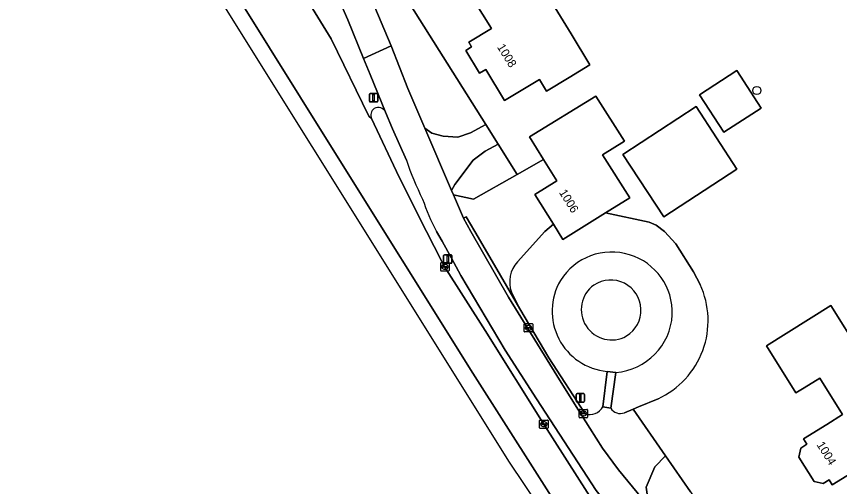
# Model space of a CAD drawing. Extents: x 157767 to 159172, y 387839 to 389425.
# Drawn here: x 158307.1 to 158404.2, y 387969.9 to 388025.4 of the extents above; entities that cross this region are included whole.
import ezdxf

# ---------------------------------------------------------------- set-up
doc = ezdxf.new("R2010")
doc.units = 0
for name, color, linetype in [('IMGEO_Berm_groen', 7, 'Continuous'), ('IMGEO_Berm_open', 7, 'Continuous'), ('IMGEO_Boom', 7, 'Continuous'), ('IMGEO_Erf', 7, 'Continuous'), ('IMGEO_Fietspad_gesloten', 7, 'Continuous'), ('IMGEO_Fietspad_open', 7, 'Continuous'), ('IMGEO_Groenvoorziening', 7, 'Continuous'), ('IMGEO_Hek', 7, 'Continuous'), ('IMGEO_Kolk', 7, 'Continuous'), ('IMGEO_Lichtmast', 7, 'Continuous'), ('IMGEO_Pand', 7, 'Continuous'), ('IMGEO_Pand_nummerreeks', 7, 'Continuous'), ('IMGEO_Rijbaan_lokaal_open', 7, 'Continuous'), ('IMGEO_Rijbaan_regionaal_gesloten', 7, 'Continuous'), ('IMGEO_Verkeersbordpaal', 7, 'Continuous'), ('IMGEO_Voetpad_halfverhard', 7, 'Continuous'), ('IMGEO_Voetpad_op_trap', 7, 'Continuous'), ('IMGEO_Voetpad_open', 7, 'Continuous')]:
    doc.layers.add(name, color=color, linetype=linetype)

msp = doc.modelspace()

# ---------------------------------------------------------------- linework, layer by layer
at = {"layer": 'IMGEO_Berm_groen'}
for points in [[(158346.988, 388032.11), (158351.304, 388021.92), (158353.257, 388016.869), (158355.265, 388012.187), (158356.096, 388011.587), (158357.419, 388011.256), (158359.167, 388011.114), (158360.678, 388011.634), (158362.458, 388012.624), (158347.36, 388036.66)], [(158346.166, 388024.99), (158343.238, 388031.743), (158341.771, 388034.966), (158338.107, 388032.717), (158344.205, 388022.734), (158348.667, 388013.632), (158348.975, 388013.341)], [(158350.634, 388014.091), (158348.806, 388018.518), (158348.022, 388020.44), (158346.166, 388024.99)]]:
    msp.add_lwpolyline(points, dxfattribs=at)
for centre, radius, start, end in [((158349.939, 388013.717), 1.034, 128.90367, 201.31806), ((158349.767, 388013.698), 0.952, 24.36885, 120.09544)]:
    msp.add_arc(centre, radius, start, end, dxfattribs=at)
at = {"layer": 'IMGEO_Berm_open'}
for points in [[(158353.103, 388008.418), (158351.446, 388012.126), (158350.634, 388014.091)], [(158348.975, 388013.341), (158352.222, 388006.425), (158355.483, 388000), (158357.278, 387996.464), (158357.565, 387995.899), (158362.406, 387988.305), (158369.454, 387977.028), (158374.434, 387969.222), (158376.58, 387965.96)], [(158368.454, 387980.231), (158364.771, 387985.981), (158359.525, 387994.789), (158358.421, 387996.854), (158357.304, 387998.859), (158356.652, 388000)], [(158377.656, 387966.667), (158375.484, 387969.385), (158368.454, 387980.231)]]:
    msp.add_lwpolyline(points, dxfattribs=at)
for centre, radius, start, end in [((158349.939, 388013.717), 1.034, 128.90367, 201.31806), ((158349.767, 388013.698), 0.952, 24.36885, 120.09544), ((158386.09, 388019.432), 34.777, 198.46324, 206.67381), ((158377.508, 388011.204), 23.675, 198.17348, 208.24543)]:
    msp.add_arc(centre, radius, start, end, dxfattribs=at)
at = {"layer": 'IMGEO_Boom'}
msp.add_circle((158394.47, 388016.645), 0.489, dxfattribs=at)
at = {"layer": 'IMGEO_Erf'}
for points in [[(158391.002, 388072.621), (158386.634, 388069.473), (158380.196, 388064.831), (158347.36, 388036.66), (158362.458, 388012.624), (158363.916, 388010.303), (158366.166, 388006.72), (158369.284, 388008.484), (158367.637, 388011.156), (158375.48, 388015.988), (158378.849, 388010.676), (158376.257, 388009.033), (158379.47, 388003.965), (158376.609, 388002.185), (158381.757, 388001.103), (158382.595, 388000.747), (158383.581, 388000), (158384.921, 387998.535), (158386.981, 387995.22), (158387.776, 387993.732)], [(158382.802, 387980.241), (158380.487, 387979.276), (158379.876, 387979.021), (158383.679, 387973.511), (158386.626, 387969.24), (158394.403, 387957.97), (158412.383, 387968.073), (158417.684, 387971.05), (158428.795, 387977.293), (158429.92, 387977.925), (158434.455, 387980.473), (158440.859, 387984.071), (158441.223, 387984.276), (158446.112, 387987.022), (158456.939, 387993.105), (158451.954, 388000), (158401.091, 388069.402)]]:
    msp.add_lwpolyline(points, dxfattribs=at)
for points in [[(158374.757, 388019.68), (158372.308, 388018.195), (158369.622, 388016.566), (158368.792, 388017.933), (158364.696, 388015.448), (158362.455, 388019.143), (158361.741, 388018.71), (158360.122, 388021.379), (158360.797, 388021.788), (158360.454, 388022.354), (158363.126, 388023.975), (158359.773, 388029.4), (158364.63, 388032.402), (158365.156, 388031.552), (158367.924, 388033.265), (158370.993, 388028.308), (158369.924, 388027.647), (158370.67, 388026.418), (158372.54, 388023.336)], [(158394.973, 388014.577), (158390.582, 388011.721), (158387.711, 388016.135), (158392.102, 388018.991)], [(158392.124, 388007.366), (158383.483, 388001.712), (158378.63, 388009.099), (158387.322, 388014.753)], [(158406.706, 387985.675), (158405.452, 387984.89), (158408.144, 387980.587), (158411.548, 387975.185), (158407.607, 387972.719), (158406.42, 387971.976), (158404.063, 387970.502), (158403.368, 387970.067), (158403.001, 387970.655), (158402.289, 387970.21), (158401.232, 387970.468), (158399.428, 387973.35), (158399.667, 387974.419), (158400.37, 387974.859), (158399.977, 387975.486), (158402.732, 387977.21), (158404.58, 387978.366), (158401.888, 387982.667), (158400.04, 387981.511), (158399.091, 387980.917), (158395.593, 387986.507), (158403.206, 387991.27)]]:
    msp.add_lwpolyline(points, close=True, dxfattribs=at)
msp.add_arc((158378.575, 387989.462), 10.144, 294.62846, 24.89466, dxfattribs=at)
at = {"layer": 'IMGEO_Fietspad_gesloten'}
msp.add_lwpolyline([(158340.514, 388037.486), (158341.063, 388036.409), (158341.771, 388034.966), (158343.238, 388031.743), (158346.166, 388024.99), (158348.022, 388020.44), (158351.304, 388021.92), (158346.988, 388032.11)], dxfattribs=at)
at = {"layer": 'IMGEO_Fietspad_open'}
for points in [[(158365.138, 387992.225), (158360.688, 387999.997), (158359.827, 388001.551), (158358.642, 388004.313), (158358.423, 388004.824), (158355.265, 388012.187), (158353.257, 388016.869), (158351.304, 388021.92), (158348.022, 388020.44), (158348.806, 388018.518), (158350.634, 388014.091), (158351.446, 388012.126), (158353.103, 388008.418)], [(158356.652, 388000), (158357.304, 387998.859), (158358.421, 387996.854), (158359.525, 387994.789), (158364.771, 387985.981), (158368.454, 387980.231), (158375.484, 387969.385), (158377.656, 387966.667), (158381.586, 387962.012), (158385.061, 387958.273), (158386.178, 387956.878), (158389.083, 387958.681), (158382.54, 387966.471), (158378.147, 387971.847), (158376.253, 387974.417), (158374.768, 387976.744), (158373.35, 387979.008), (158370.858, 387982.984), (158365.138, 387992.225)]]:
    msp.add_lwpolyline(points, dxfattribs=at)
for centre, radius, start, end in [((158386.09, 388019.432), 34.777, 198.46324, 206.67381), ((158377.508, 388011.204), 23.675, 198.17348, 208.24543)]:
    msp.add_arc(centre, radius, start, end, dxfattribs=at)
at = {"layer": 'IMGEO_Groenvoorziening'}
msp.add_lwpolyline([(158358.642, 388004.313), (158361.035, 388003.817), (158366.166, 388006.72), (158363.916, 388010.303), (158362.379, 388009.46), (158360.962, 388008.42), (158358.815, 388005.531), (158358.423, 388004.824)], close=True, dxfattribs=at)
for points in [[(158383.581, 388000), (158382.595, 388000.747), (158381.757, 388001.103), (158376.609, 388002.185), (158371.564, 387999.047), (158370.45, 388000.838), (158369.425, 388000), (158366.221, 387996.405)], [(158387.776, 387993.732), (158386.981, 387995.22), (158384.921, 387998.535), (158383.581, 388000)], [(158365.501, 387992.822), (158366.481, 387990.875), (158369.912, 387985.089), (158374.192, 387978.444)], [(158376.292, 387979.293), (158376.782, 387983.471)], [(158377.816, 387983.342), (158377.221, 387979.137)], [(158378.836, 387978.588), (158379.876, 387979.021), (158380.487, 387979.276), (158382.802, 387980.241)], [(158386.626, 387969.24), (158383.679, 387973.511), (158382.408, 387972.2), (158381.416, 387969.789), (158381.605, 387968.419), (158381.816, 387967.785), (158382.54, 387966.471), (158389.083, 387958.681), (158390.866, 387956.568), (158394.093, 387952.069), (158438.678, 387886.742), (158446.315, 387875.553), (158447.84, 387876.589), (158451.143, 387878.831), (158405.61, 387947.322)]]:
    msp.add_lwpolyline(points, dxfattribs=at)
for centre, radius, start, end in [((158377.347, 387990.422), 7.145, 357.84095, 148.02132), ((158368.759, 387994.031), 3.475, 136.91356, 200.36204), ((158377.438, 387990.581), 7.14, 149.48772, 264.72601), ((158378.575, 387989.462), 10.144, 294.62846, 24.89466), ((158377.254, 387990.564), 7.244, 274.44555, 356.74435), ((158374.723, 387980.153), 1.79, 252.75877, 331.26679), ((158378.356, 387979.827), 1.329, 211.28641, 291.16389)]:
    msp.add_arc(centre, radius, start, end, dxfattribs=at)
at = {"layer": 'IMGEO_Hek'}
for points in [[(158383.679, 387973.511), (158379.876, 387979.021)], [(158386.626, 387969.24), (158383.679, 387973.511)]]:
    msp.add_lwpolyline(points, dxfattribs=at)
at = {"layer": 'IMGEO_Kolk'}
for p, q in [((158357.143, 387995.396), (158357.143, 387996.248)), ((158357.218, 387996.322), (158358.07, 387996.322)), ((158357.402, 387995.816), (158357.402, 387995.828)), ((158357.84, 387995.779), (158357.442, 387995.779)), ((158357.445, 387995.865), (158357.843, 387995.865)), ((158357.631, 387996.102), (158357.656, 387996.102)), ((158357.886, 387995.828), (158357.886, 387995.816)), ((158358.144, 387996.248), (158358.144, 387995.396)), ((158358.07, 387995.322), (158357.218, 387995.322)), ((158357.654, 387995.542), (158357.629, 387995.542)), ((158367.009, 387988.198), (158367.009, 387989.05)), ((158367.084, 387989.124), (158367.936, 387989.124)), ((158367.497, 387988.904), (158367.522, 387988.904)), ((158368.01, 387989.05), (158368.01, 387988.198)), ((158367.936, 387988.124), (158367.084, 387988.124)), ((158367.268, 387988.618), (158367.268, 387988.63)), ((158367.706, 387988.581), (158367.308, 387988.581)), ((158367.311, 387988.667), (158367.709, 387988.667)), ((158367.52, 387988.344), (158367.495, 387988.344)), ((158367.752, 387988.63), (158367.752, 387988.618)), ((158373.481, 387978.058), (158373.481, 387978.91)), ((158373.556, 387978.984), (158374.408, 387978.984)), ((158373.74, 387978.478), (158373.74, 387978.49)), ((158374.178, 387978.441), (158373.78, 387978.441)), ((158373.783, 387978.527), (158374.181, 387978.527)), ((158373.992, 387978.204), (158373.967, 387978.204)), ((158373.969, 387978.764), (158373.994, 387978.764)), ((158374.224, 387978.49), (158374.224, 387978.478)), ((158374.482, 387978.91), (158374.482, 387978.058)), ((158368.824, 387976.801), (158368.824, 387977.653)), ((158368.899, 387977.727), (158369.751, 387977.727)), ((158369.083, 387977.221), (158369.083, 387977.233)), ((158369.521, 387977.184), (158369.123, 387977.184)), ((158369.126, 387977.27), (158369.524, 387977.27)), ((158369.312, 387977.507), (158369.337, 387977.507)), ((158369.567, 387977.233), (158369.567, 387977.221)), ((158369.825, 387977.653), (158369.825, 387976.801)), ((158374.408, 387977.984), (158373.556, 387977.984)), ((158369.751, 387976.727), (158368.899, 387976.727)), ((158369.335, 387976.947), (158369.31, 387976.947))]:
    msp.add_line(p, q, dxfattribs=at)
for points in [[(158357.143, 387995.396), (158357.143, 387996.248)], [(158357.218, 387996.322), (158358.07, 387996.322)], [(158358.144, 387996.248), (158358.144, 387995.396)], [(158358.07, 387995.322), (158357.218, 387995.322)], [(158367.009, 387988.198), (158367.009, 387989.05)], [(158367.084, 387989.124), (158367.936, 387989.124)], [(158368.01, 387989.05), (158368.01, 387988.198)], [(158367.936, 387988.124), (158367.084, 387988.124)], [(158373.481, 387978.058), (158373.481, 387978.91)], [(158373.556, 387978.984), (158374.408, 387978.984)], [(158374.482, 387978.91), (158374.482, 387978.058)], [(158368.824, 387976.801), (158368.824, 387977.653)], [(158368.899, 387977.727), (158369.751, 387977.727)], [(158369.825, 387977.653), (158369.825, 387976.801)], [(158374.408, 387977.984), (158373.556, 387977.984)], [(158369.751, 387976.727), (158368.899, 387976.727)]]:
    msp.add_lwpolyline(points, dxfattribs=at)
for centre, radius, start, end in [((158357.22, 387996.246), 0.0765, 91.55205, 178.44795), ((158357.22, 387996.246), 0.0765, 91.55205, 178.44795), ((158357.442, 387995.825), 0.0403, 85.87752, 175.75265), ((158357.439, 387995.815), 0.0366, 178.93798, 274.71019), ((158357.843, 387995.822), 0.043, 264.86636, 352.45326), ((158357.847, 387995.827), 0.0386, 1.73085, 96.63898), ((158358.068, 387996.246), 0.0765, 1.55205, 88.44795), ((158358.068, 387996.246), 0.0765, 1.55205, 88.44795), ((158357.22, 387995.398), 0.0765, 181.55205, 268.44795), ((158357.22, 387995.398), 0.0765, 181.55205, 268.44795), ((158358.068, 387995.398), 0.0765, 271.55205, 358.44795), ((158358.068, 387995.398), 0.0765, 271.55205, 358.44795), ((158367.086, 387989.048), 0.0765, 91.55205, 178.44795), ((158367.086, 387989.048), 0.0765, 91.55205, 178.44795), ((158367.934, 387989.048), 0.0765, 1.55205, 88.44795), ((158367.934, 387989.048), 0.0765, 1.55205, 88.44795), ((158367.086, 387988.2), 0.0765, 181.55205, 268.44795), ((158367.086, 387988.2), 0.0765, 181.55205, 268.44795), ((158367.308, 387988.627), 0.0403, 85.87752, 175.75265), ((158367.305, 387988.617), 0.0366, 178.93798, 274.71019), ((158367.709, 387988.624), 0.043, 264.86636, 352.45326), ((158367.713, 387988.629), 0.0386, 1.73085, 96.63898), ((158367.934, 387988.2), 0.0765, 271.55205, 358.44795), ((158367.934, 387988.2), 0.0765, 271.55205, 358.44795), ((158373.558, 387978.908), 0.0765, 91.55205, 178.44795), ((158373.558, 387978.908), 0.0765, 91.55205, 178.44795), ((158373.78, 387978.487), 0.0403, 85.87752, 175.75265), ((158373.777, 387978.477), 0.0366, 178.93798, 274.71019), ((158374.181, 387978.484), 0.043, 264.86636, 352.45326), ((158374.185, 387978.489), 0.0386, 1.73085, 96.63898), ((158374.406, 387978.908), 0.0765, 1.55205, 88.44795), ((158374.406, 387978.908), 0.0765, 1.55205, 88.44795), ((158368.901, 387977.651), 0.0765, 91.55205, 178.44795), ((158368.901, 387977.651), 0.0765, 91.55205, 178.44795), ((158369.123, 387977.23), 0.0403, 85.87752, 175.75265), ((158369.12, 387977.22), 0.0366, 178.93798, 274.71019), ((158369.524, 387977.227), 0.043, 264.86636, 352.45326), ((158369.528, 387977.232), 0.0386, 1.73085, 96.63898), ((158369.749, 387977.651), 0.0765, 1.55205, 88.44795), ((158369.749, 387977.651), 0.0765, 1.55205, 88.44795), ((158373.558, 387978.06), 0.0765, 181.55205, 268.44795), ((158373.558, 387978.06), 0.0765, 181.55205, 268.44795), ((158374.406, 387978.06), 0.0765, 271.55205, 358.44795), ((158374.406, 387978.06), 0.0765, 271.55205, 358.44795), ((158368.901, 387976.803), 0.0765, 181.55205, 268.44795), ((158368.901, 387976.803), 0.0765, 181.55205, 268.44795), ((158369.749, 387976.803), 0.0765, 271.55205, 358.44795), ((158369.749, 387976.803), 0.0765, 271.55205, 358.44795)]:
    msp.add_arc(centre, radius, start, end, dxfattribs=at)
for centre, major_axis, ratio, start_param, end_param in [((158357.63, 387995.822), (-0.387, 0.002), 0.722429, 4.712389, 7.853982), ((158357.655, 387995.822), (-0.39, 0.002), 0.717154, 1.570796, 4.712389), ((158367.496, 387988.624), (-0.387, 0.002), 0.722429, 4.712389, 7.853982), ((158367.521, 387988.624), (-0.39, 0.002), 0.717154, 1.570796, 4.712389), ((158373.968, 387978.484), (-0.387, 0.002), 0.722429, 4.712389, 7.853982), ((158373.993, 387978.484), (-0.39, 0.002), 0.717154, 1.570796, 4.712389), ((158369.311, 387977.227), (-0.387, 0.002), 0.722429, 4.712389, 7.853982), ((158369.336, 387977.227), (-0.39, 0.002), 0.717154, 1.570796, 4.712389)]:
    msp.add_ellipse(centre, major_axis=major_axis, ratio=ratio, start_param=start_param, end_param=end_param, dxfattribs=at)
at = {"layer": 'IMGEO_Lichtmast'}
for p, q in [((158357.488, 387996.337), (158357.488, 387997.137)), ((158357.488, 387997.137), (158357.488, 387996.337)), ((158357.588, 387997.237), (158358.378, 387997.237)), ((158358.378, 387997.237), (158357.588, 387997.237)), ((158358.478, 387997.137), (158358.478, 387996.337)), ((158358.478, 387996.337), (158358.478, 387997.137)), ((158358.378, 387996.237), (158357.588, 387996.237)), ((158357.588, 387996.237), (158358.378, 387996.237)), ((158373.139, 387979.946), (158373.139, 387980.746)), ((158373.139, 387980.746), (158373.139, 387979.946)), ((158373.239, 387980.846), (158374.029, 387980.846)), ((158374.029, 387980.846), (158373.239, 387980.846)), ((158374.129, 387980.746), (158374.129, 387979.946)), ((158374.129, 387979.946), (158374.129, 387980.746)), ((158374.029, 387979.846), (158373.239, 387979.846)), ((158373.239, 387979.846), (158374.029, 387979.846))]:
    msp.add_line(p, q, dxfattribs=at)
for points in [[(158357.908, 387997.112), (158358.058, 387997.112), (158358.058, 387996.362), (158357.908, 387996.362), (158357.908, 387997.112)], [(158373.559, 387980.721), (158373.709, 387980.721), (158373.709, 387979.971), (158373.559, 387979.971), (158373.559, 387980.721)]]:
    msp.add_lwpolyline(points, dxfattribs=at)
for centre, start, end in [((158357.588, 387997.137), 90, 180), ((158357.588, 387997.137), 90, 180), ((158358.378, 387997.137), 0, 90), ((158358.378, 387997.137), 360, 90), ((158357.588, 387996.337), 180, 270), ((158357.588, 387996.337), 180, 270), ((158358.378, 387996.337), 270, 0), ((158358.378, 387996.337), 270, 0), ((158373.239, 387980.746), 90, 180), ((158373.239, 387980.746), 90, 180), ((158374.029, 387980.746), 0, 90), ((158374.029, 387980.746), 360, 90), ((158373.239, 387979.946), 180, 270), ((158373.239, 387979.946), 180, 270), ((158374.029, 387979.946), 270, 0), ((158374.029, 387979.946), 270, 0)]:
    msp.add_arc(centre, 0.1, start, end, dxfattribs=at)
at = {"layer": 'IMGEO_Pand'}
for points in [[(158372.54, 388023.336), (158370.67, 388026.418), (158369.924, 388027.647), (158370.993, 388028.308), (158367.924, 388033.265), (158365.156, 388031.552), (158364.63, 388032.402), (158359.773, 388029.4), (158363.126, 388023.975), (158360.454, 388022.354), (158360.797, 388021.788), (158360.122, 388021.379), (158361.741, 388018.71), (158362.455, 388019.143), (158364.696, 388015.448), (158368.792, 388017.933), (158369.622, 388016.566), (158372.308, 388018.195), (158374.757, 388019.68)], [(158387.711, 388016.135), (158390.582, 388011.721), (158394.973, 388014.577), (158392.102, 388018.991)], [(158379.47, 388003.965), (158376.257, 388009.033), (158378.849, 388010.676), (158375.48, 388015.988), (158367.637, 388011.156), (158369.284, 388008.484), (158370.841, 388005.96), (158368.25, 388004.376), (158370.45, 388000.838), (158371.564, 387999.047), (158376.609, 388002.185)], [(158383.483, 388001.712), (158392.124, 388007.366), (158387.322, 388014.753), (158378.63, 388009.099)], [(158406.42, 387971.976), (158407.607, 387972.719), (158411.548, 387975.185), (158408.144, 387980.587), (158405.452, 387984.89), (158406.706, 387985.675), (158403.206, 387991.27), (158395.593, 387986.507), (158399.091, 387980.917), (158400.04, 387981.511), (158401.888, 387982.667), (158404.58, 387978.366), (158402.732, 387977.21), (158399.977, 387975.486), (158400.37, 387974.859), (158399.667, 387974.419), (158399.428, 387973.35), (158401.232, 387970.468), (158402.289, 387970.21), (158403.001, 387970.655), (158403.368, 387970.067), (158404.063, 387970.502)]]:
    msp.add_lwpolyline(points, close=True, dxfattribs=at)
for centre, radius, start, end in [((158377.324, 387990.762), 3.578, 125.65627, 299.58005), ((158377.213, 387990.691), 3.574, 301.68499, 123.55133)]:
    msp.add_arc(centre, radius, start, end, dxfattribs=at)
at = {"layer": 'IMGEO_Rijbaan_lokaal_open'}
msp.add_lwpolyline([(158362.379, 388009.46), (158363.916, 388010.303), (158362.458, 388012.624), (158360.678, 388011.634), (158359.167, 388011.114), (158357.419, 388011.256), (158356.096, 388011.587), (158355.265, 388012.187), (158358.423, 388004.824), (158358.815, 388005.531), (158360.962, 388008.42)], close=True, dxfattribs=at)
at = {"layer": 'IMGEO_Rijbaan_regionaal_gesloten'}
msp.add_lwpolyline([(158451.495, 387844.239), (158452.803, 387845.02), (158451.525, 387846.948), (158442.147, 387860.938), (158426.868, 387883.332), (158408.412, 387910.456), (158399.457, 387923.695), (158386.757, 387942.891), (158379.772, 387953.65), (158360.952, 387983.276), (158344.038, 388010.284), (158333.452, 388027.227), (158314.654, 388057.246), (158299.748, 388081.131), (158276.299, 388118.666), (158263.511, 388139.131), (158246.505, 388166.455), (158235.872, 388183.535), (158227.894, 388196.396), (158226.486, 388195.55), (158248.484, 388159.503), (158365.233, 387972.762)], close=True, dxfattribs=at)
for points in [[(158344.205, 388022.734), (158338.107, 388032.717), (158337.771, 388033.267), (158332.851, 388041.162), (158328.755, 388047.903), (158325.725, 388052.558), (158321.212, 388059.594), (158320.866, 388060.134), (158319.396, 388062.058), (158314.258, 388068.698), (158308.615, 388075.824), (158303.622, 388082.558), (158299.296, 388088.955), (158293.547, 388097.926), (158289.422, 388105.178), (158287.382, 388107.215), (158278.58, 388121.287), (158245.322, 388174.532)], [(158246.505, 388166.455), (158263.511, 388139.131), (158276.299, 388118.666), (158299.748, 388081.131), (158314.654, 388057.246), (158333.452, 388027.227), (158344.038, 388010.284), (158360.952, 387983.276), (158379.772, 387953.65), (158386.757, 387942.891), (158399.457, 387923.695), (158408.412, 387910.456), (158426.868, 387883.332), (158442.147, 387860.938), (158451.525, 387846.948), (158452.803, 387845.02), (158456.206, 387847.053), (158455.2, 387848.498), (158450.464, 387855.42)], [(158449.319, 387857.167), (158446.563, 387860.234), (158431.39, 387882.66), (158411.064, 387912.614), (158394.357, 387937.667), (158391.119, 387943.609), (158384.484, 387953.68), (158376.58, 387965.96), (158374.434, 387969.222), (158369.454, 387977.028), (158362.406, 387988.305), (158357.565, 387995.899), (158357.278, 387996.464), (158355.483, 388000), (158352.222, 388006.425), (158348.975, 388013.341), (158348.667, 388013.632), (158344.205, 388022.734)]]:
    msp.add_lwpolyline(points, dxfattribs=at)
at = {"layer": 'IMGEO_Verkeersbordpaal'}
for p, q in [((158348.723, 388015.392), (158348.723, 388016.192)), ((158348.723, 388016.192), (158348.723, 388015.392)), ((158348.823, 388016.292), (158349.613, 388016.292)), ((158349.613, 388016.292), (158348.823, 388016.292)), ((158349.713, 388016.192), (158349.713, 388015.392)), ((158349.713, 388015.392), (158349.713, 388016.192)), ((158349.613, 388015.292), (158348.823, 388015.292)), ((158348.823, 388015.292), (158349.613, 388015.292))]:
    msp.add_line(p, q, dxfattribs=at)
msp.add_lwpolyline([(158349.143, 388016.167), (158349.293, 388016.167), (158349.293, 388015.417), (158349.143, 388015.417), (158349.143, 388016.167)], dxfattribs=at)
for centre, start, end in [((158348.823, 388016.192), 90, 180), ((158348.823, 388016.192), 90, 180), ((158349.613, 388016.192), 0, 90), ((158349.613, 388016.192), 360, 90), ((158348.823, 388015.392), 180, 270), ((158348.823, 388015.392), 180, 270), ((158349.613, 388015.392), 270, 0), ((158349.613, 388015.392), 270, 0)]:
    msp.add_arc(centre, 0.1, start, end, dxfattribs=at)
at = {"layer": 'IMGEO_Voetpad_halfverhard'}
msp.add_lwpolyline([(158376.782, 387983.471), (158377.816, 387983.342)], dxfattribs=at)
for centre, radius, start, end in [((158377.347, 387990.422), 7.145, 357.84095, 148.02132), ((158377.438, 387990.581), 7.14, 149.48772, 264.72601), ((158377.324, 387990.762), 3.578, 125.65627, 299.58005), ((158377.213, 387990.691), 3.574, 301.68499, 123.55133), ((158377.254, 387990.564), 7.244, 274.44555, 356.74435)]:
    msp.add_arc(centre, radius, start, end, dxfattribs=at)
at = {"layer": 'IMGEO_Voetpad_op_trap'}
msp.add_lwpolyline([(158377.816, 387983.342), (158376.782, 387983.471), (158376.292, 387979.293), (158377.221, 387979.137)], close=True, dxfattribs=at)
at = {"layer": 'IMGEO_Voetpad_open'}
for points in [[(158366.221, 387996.405), (158369.425, 388000), (158370.45, 388000.838), (158368.25, 388004.376), (158370.841, 388005.96), (158369.284, 388008.484), (158366.166, 388006.72), (158361.035, 388003.817), (158358.642, 388004.313), (158359.827, 388001.551), (158360.148, 388001.729), (158361.157, 388000), (158363.764, 387995.531), (158366.481, 387990.875), (158365.501, 387992.822)], [(158363.764, 387995.531), (158361.157, 388000), (158360.148, 388001.729), (158359.827, 388001.551), (158360.688, 387999.997), (158365.138, 387992.225), (158370.858, 387982.984), (158373.35, 387979.008)], [(158374.192, 387978.444), (158369.912, 387985.089), (158366.481, 387990.875), (158363.764, 387995.531)], [(158377.221, 387979.137), (158376.292, 387979.293)], [(158373.35, 387979.008), (158374.768, 387976.744), (158376.253, 387974.417), (158378.147, 387971.847), (158382.54, 387966.471), (158381.816, 387967.785), (158381.605, 387968.419), (158381.416, 387969.789), (158382.408, 387972.2), (158383.679, 387973.511), (158379.876, 387979.021)], [(158379.876, 387979.021), (158378.836, 387978.588)]]:
    msp.add_lwpolyline(points, dxfattribs=at)
for centre, radius, start, end in [((158368.759, 387994.031), 3.475, 136.91356, 200.36204), ((158374.723, 387980.153), 1.79, 252.75877, 331.26679), ((158378.356, 387979.827), 1.329, 211.28641, 291.16389), ((158374.723, 387980.147), 1.783, 219.67844, 252.69054), ((158374.723, 387980.147), 1.783, 219.67844, 252.69054)]:
    msp.add_arc(centre, radius, start, end, dxfattribs=at)

# ---------------------------------------------------------------- texts
at = {"layer": 'IMGEO_Pand_nummerreeks'}
for s, rotation, p in [('1008', 301.56026, (158363.762, 388021.784)), ('1006', 301.87667, (158371.078, 388004.601)), ('1004', 302.04468, (158401.49, 387974.805))]:
    msp.add_text(s, height=1, rotation=rotation, dxfattribs=at).set_placement(p)

doc.saveas('drawing.dxf')
